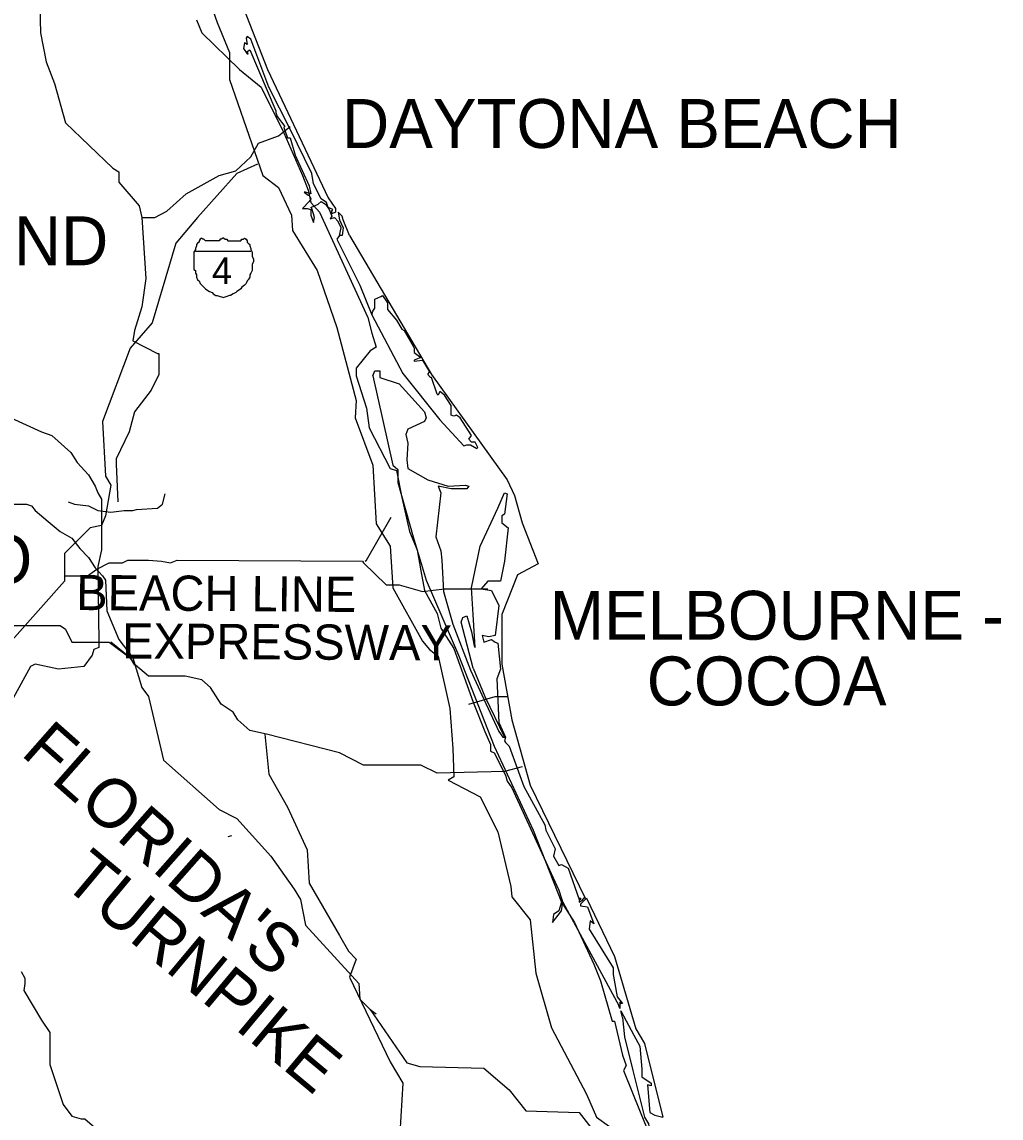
# Model space of a CAD drawing. Extents: x -827.9 to -798.1, y -2199.1 to -2182.2.
# Drawn here: x -805.79 to -804.889, y -2184.917 to -2183.909 of the extents above; entities that cross this region are included whole.
import ezdxf

# ---------------------------------------------------------------- set-up
doc = ezdxf.new("R2010")
doc.units = 0
for name, color, linetype in [('FLMap1', 7, 'Continuous'), ('FLMap2', 7, 'Continuous'), ('FLMap3', 7, 'Continuous'), ('TextMisc', 7, 'Continuous')]:
    doc.layers.add(name, color=color, linetype=linetype)

msp = doc.modelspace()

# ---------------------------------------------------------------- linework, layer by layer
at = {"layer": 'FLMap1'}
msp.add_line((-805.63, -2184.1195), (-805.5789, -2184.1195), dxfattribs=at)
for points in [[(-805.6037, -2184.1076), (-805.6047, -2184.1076), (-805.6062, -2184.1086), (-805.6072, -2184.1086), (-805.6082, -2184.1101), (-805.6101, -2184.1101), (-805.6111, -2184.1101), (-805.6126, -2184.1101), (-805.6136, -2184.1101), (-805.6146, -2184.1101), (-805.6161, -2184.1101), (-805.6171, -2184.1101), (-805.6186, -2184.1101), (-805.6206, -2184.1101), (-805.6221, -2184.1086), (-805.623, -2184.1086), (-805.624, -2184.1076), (-805.6255, -2184.1086), (-805.6265, -2184.1101), (-805.6265, -2184.1111), (-805.628, -2184.1121), (-805.629, -2184.1135), (-805.629, -2184.1145), (-805.63, -2184.117), (-805.63, -2184.118), (-805.6315, -2184.1205), (-805.6315, -2184.123), (-805.6315, -2184.124), (-805.6315, -2184.1269), (-805.6315, -2184.1294), (-805.6315, -2184.1314), (-805.6315, -2184.1339), (-805.6315, -2184.1364), (-805.63, -2184.1374), (-805.63, -2184.1398), (-805.629, -2184.1413), (-805.629, -2184.1433), (-805.628, -2184.1458), (-805.6265, -2184.1468), (-805.6255, -2184.1493), (-805.624, -2184.1508), (-805.6221, -2184.1527), (-805.6206, -2184.1542), (-805.6196, -2184.1552), (-805.6171, -2184.1567), (-805.6146, -2184.1577), (-805.6136, -2184.1587), (-805.6111, -2184.1602), (-805.6101, -2184.1602), (-805.6072, -2184.1612), (-805.6037, -2184.1622)], [(-805.6037, -2184.1076), (-805.6037, -2184.1076), (-805.6027, -2184.1086), (-805.6012, -2184.1086), (-805.6002, -2184.1101), (-805.5987, -2184.1101), (-805.5977, -2184.1101), (-805.5968, -2184.1101), (-805.5953, -2184.1101), (-805.5943, -2184.1101), (-805.5928, -2184.1101), (-805.5918, -2184.1101), (-805.5908, -2184.1101), (-805.5883, -2184.1101), (-805.5873, -2184.1086), (-805.5858, -2184.1086), (-805.5848, -2184.1076), (-805.5834, -2184.1086), (-805.5824, -2184.1101), (-805.5824, -2184.1111), (-805.5814, -2184.1121), (-805.5799, -2184.1135), (-805.5799, -2184.1145), (-805.5789, -2184.117), (-805.5789, -2184.118), (-805.5779, -2184.1205), (-805.5779, -2184.123), (-805.5779, -2184.124), (-805.5764, -2184.1269), (-805.5764, -2184.1294), (-805.5779, -2184.1314), (-805.5779, -2184.1339), (-805.5779, -2184.1364), (-805.5779, -2184.1374), (-805.5789, -2184.1398), (-805.5799, -2184.1413), (-805.5799, -2184.1433), (-805.5814, -2184.1458), (-805.5824, -2184.1468), (-805.5834, -2184.1493), (-805.5848, -2184.1508), (-805.5873, -2184.1527), (-805.5883, -2184.1542), (-805.5893, -2184.1552), (-805.5918, -2184.1567), (-805.5928, -2184.1577), (-805.5953, -2184.1587), (-805.5977, -2184.1602), (-805.5987, -2184.1602), (-805.6012, -2184.1612), (-805.6037, -2184.1622)]]:
    msp.add_lwpolyline(points, dxfattribs=at)
at = {"layer": 'FLMap2'}
for points in [[(-805.6444, -2183.7459), (-805.5635, -2183.9523)], [(-805.7734, -2183.8828), (-805.7724, -2183.9186), (-805.7674, -2183.9454), (-805.7595, -2183.9652), (-805.7496, -2184.0014), (-805.7059, -2184.0431), (-805.7004, -2184.0466), (-805.7004, -2184.056), (-805.6816, -2184.0778), (-805.6791, -2184.0887), (-805.6756, -2184.1448), (-805.6791, -2184.1706), (-805.6861, -2184.1924), (-805.6875, -2184.2019), (-805.6647, -2184.2138), (-805.6637, -2184.2138), (-805.6637, -2184.2331), (-805.6707, -2184.2475), (-805.6861, -2184.2673), (-805.691, -2184.2857), (-805.7029, -2184.3105)], [(-805.629, -2183.9067), (-805.624, -2183.9186), (-805.5893, -2183.9523), (-805.5695, -2183.9687), (-805.5486, -2184.0108), (-805.5313, -2184.05), (-805.5263, -2184.0634), (-805.5238, -2184.0748), (-805.5159, -2184.0838), (-805.4712, -2184.1805), (-805.4678, -2184.1949), (-805.4638, -2184.2078), (-805.4692, -2184.2113), (-805.4821, -2184.2272)], [(-805.5427, -2184.0074), (-805.5625, -2183.9687), (-805.5789, -2183.9245), (-805.5824, -2183.922), (-805.5834, -2183.9235), (-805.5824, -2183.9295), (-805.5848, -2183.928), (-805.5858, -2183.933), (-805.5824, -2183.9379), (-805.5814, -2183.9379), (-805.5824, -2183.9359), (-805.5799, -2183.9344), (-805.5561, -2183.9905), (-805.5561, -2183.992), (-805.5546, -2183.9955), (-805.5476, -2184.0049)], [(-805.5635, -2183.9523), (-805.5079, -2184.0704), (-805.501, -2184.0803), (-805.501, -2184.0838), (-805.5045, -2184.0853)], [(-805.6791, -2184.0887), (-805.6672, -2184.0887), (-805.6563, -2184.0828), (-805.6384, -2184.0669), (-805.6082, -2184.05), (-805.5928, -2184.0456), (-805.5789, -2184.0327), (-805.5719, -2184.0203), (-805.5536, -2184.0133), (-805.5427, -2184.0049)], [(-805.5476, -2184.0049), (-805.5486, -2184.0059), (-805.5452, -2184.0153), (-805.5427, -2184.0153), (-805.5382, -2184.0312), (-805.5253, -2184.0595), (-805.5238, -2184.0669), (-805.5288, -2184.0654), (-805.5298, -2184.0654), (-805.5263, -2184.0679), (-805.5253, -2184.0679), (-805.5238, -2184.0714), (-805.5253, -2184.0739), (-805.5313, -2184.0803), (-805.5273, -2184.0803), (-805.5238, -2184.0813), (-805.5238, -2184.0863), (-805.5213, -2184.0932), (-805.5203, -2184.0887), (-805.5213, -2184.0853), (-805.5228, -2184.0803), (-805.5238, -2184.0793), (-805.5169, -2184.0763), (-805.5144, -2184.0739), (-805.5104, -2184.0763), (-805.507, -2184.0813), (-805.5045, -2184.0872), (-805.506, -2184.0897), (-805.502, -2184.0887), (-805.4985, -2184.0922)], [(-805.5045, -2184.0853), (-805.5045, -2184.0828), (-805.5035, -2184.0813), (-805.5079, -2184.0793), (-805.5094, -2184.0748), (-805.5144, -2184.0714), (-805.5213, -2184.0575), (-805.5228, -2184.0481), (-805.5427, -2184.0074)], [(-805.4881, -2184.1051), (-805.4941, -2184.0907), (-805.495, -2184.0872), (-805.4985, -2184.0838), (-805.4975, -2184.0907), (-805.4941, -2184.0982), (-805.495, -2184.1051), (-805.4975, -2184.1051), (-805.496, -2184.0982), (-805.4985, -2184.0922)], [(-805.4975, -2184.1051), (-805.5, -2184.1086), (-805.4787, -2184.1508), (-805.4678, -2184.178)], [(-805.4881, -2184.1051), (-805.4127, -2184.2331), (-805.3432, -2184.3299), (-805.3363, -2184.3442), (-805.3293, -2184.3695), (-805.3145, -2184.4072), (-805.3338, -2184.4172), (-805.3482, -2184.4539), (-805.3482, -2184.4995), (-805.3388, -2184.5506), (-805.3219, -2184.6107), (-805.2713, -2184.7148)], [(-805.4678, -2184.178), (-805.4668, -2184.1746), (-805.4648, -2184.1721), (-805.4648, -2184.1637), (-805.4593, -2184.1612), (-805.4578, -2184.1602), (-805.4534, -2184.1671), (-805.4534, -2184.1731), (-805.4449, -2184.183), (-805.44, -2184.1914), (-805.438, -2184.1924), (-805.4296, -2184.2068), (-805.4286, -2184.2088), (-805.4286, -2184.2128), (-805.4226, -2184.2172), (-805.4286, -2184.2197), (-805.4286, -2184.2207), (-805.4211, -2184.2197), (-805.4147, -2184.2306)], [(-805.4678, -2184.178), (-805.439, -2184.2321), (-805.4052, -2184.2748), (-805.3829, -2184.2986)], [(-805.4821, -2184.2272), (-805.4821, -2184.2341), (-805.4727, -2184.2639), (-805.4702, -2184.2822), (-805.4509, -2184.3194), (-805.4449, -2184.3214), (-805.44, -2184.3462), (-805.433, -2184.3775), (-805.4261, -2184.3944), (-805.4226, -2184.4137), (-805.4191, -2184.4316), (-805.4077, -2184.4529), (-805.4043, -2184.4663), (-805.3923, -2184.4851), (-805.3745, -2184.5343), (-805.3636, -2184.5615), (-805.3586, -2184.5735), (-805.3586, -2184.5794), (-805.3551, -2184.5809), (-805.3447, -2184.6017), (-805.3432, -2184.6072), (-805.3388, -2184.6131), (-805.2956, -2184.7074), (-805.2911, -2184.7218)], [(-805.4668, -2184.2341), (-805.4648, -2184.2296), (-805.4603, -2184.2296), (-805.4603, -2184.2356), (-805.4425, -2184.2415), (-805.4191, -2184.2673), (-805.4177, -2184.2728), (-805.4191, -2184.2763)], [(-805.4668, -2184.2341), (-805.4484, -2184.3165), (-805.4439, -2184.3204), (-805.4439, -2184.3323), (-805.4296, -2184.3824), (-805.4177, -2184.4221), (-805.3879, -2184.4911), (-805.3551, -2184.5749), (-805.3194, -2184.6523), (-805.2931, -2184.7183)], [(-805.4008, -2184.252), (-805.4052, -2184.2485), (-805.4067, -2184.252), (-805.4077, -2184.251), (-805.4127, -2184.2356), (-805.4137, -2184.2356), (-805.4162, -2184.2331), (-805.4147, -2184.2306)], [(-805.3829, -2184.2986), (-805.3804, -2184.2976), (-805.377, -2184.2976), (-805.371, -2184.3011), (-805.37, -2184.3001), (-805.3725, -2184.2951), (-805.376, -2184.2951), (-805.3785, -2184.2926), (-805.376, -2184.2892), (-805.3864, -2184.2728), (-805.3899, -2184.2703), (-805.3923, -2184.2713), (-805.3948, -2184.2703), (-805.3948, -2184.2614), (-805.4008, -2184.252)], [(-805.7997, -2184.2728), (-805.7714, -2184.2857), (-805.762, -2184.2892), (-805.7446, -2184.3046), (-805.7386, -2184.314), (-805.7282, -2184.3254)], [(-805.4191, -2184.2763), (-805.4345, -2184.2832), (-805.4365, -2184.2882), (-805.4345, -2184.2961), (-805.4355, -2184.3115), (-805.4345, -2184.3194), (-805.4162, -2184.3299), (-805.3973, -2184.3358), (-805.3819, -2184.3348), (-805.3785, -2184.3358), (-805.3804, -2184.3383), (-805.3948, -2184.3383), (-805.4067, -2184.3358), (-805.4043, -2184.3418), (-805.4087, -2184.3824)], [(-805.7029, -2184.3105), (-805.7029, -2184.3155), (-805.7014, -2184.3502)], [(-805.7282, -2184.3254), (-805.7223, -2184.3358), (-805.7198, -2184.3418), (-805.7163, -2184.3477), (-805.7163, -2184.3681), (-805.7163, -2184.3944), (-805.7198, -2184.4097), (-805.7188, -2184.4792), (-805.7188, -2184.4841), (-805.7233, -2184.4861), (-805.7248, -2184.4911), (-805.7327, -2184.5015), (-805.756, -2184.504), (-805.7773, -2184.4995), (-805.7818, -2184.5015), (-805.8046, -2184.5437), (-805.8061, -2184.5506), (-805.8131, -2184.57), (-805.8141, -2184.5829), (-805.8344, -2184.5829), (-805.8547, -2184.5854), (-805.8622, -2184.5888)], [(-805.3745, -2184.503), (-805.3854, -2184.4608), (-805.3839, -2184.4564), (-805.3804, -2184.4549), (-805.376, -2184.4698), (-805.3735, -2184.4827), (-805.3725, -2184.4841), (-805.3745, -2184.4539), (-805.376, -2184.4291), (-805.368, -2184.3909), (-805.3517, -2184.3561), (-805.3457, -2184.3418), (-805.3432, -2184.3428), (-805.3457, -2184.3616), (-805.3482, -2184.3631), (-805.3482, -2184.3695), (-805.3422, -2184.374), (-805.3457, -2184.4048), (-805.3492, -2184.4231), (-805.3611, -2184.4231), (-805.367, -2184.4301), (-805.3576, -2184.4316), (-805.3507, -2184.4455), (-805.3541, -2184.4732), (-805.3601, -2184.4742), (-805.3661, -2184.4732), (-805.3646, -2184.4792), (-805.3576, -2184.4767), (-805.3541, -2184.4792), (-805.3517, -2184.4802), (-805.3492, -2184.504)], [(-805.4087, -2184.3824), (-805.4043, -2184.3953), (-805.4033, -2184.4038), (-805.4018, -2184.4326), (-805.3933, -2184.4628), (-805.377, -2184.505)], [(-805.8121, -2184.4549), (-805.8026, -2184.4638), (-805.7545, -2184.4638), (-805.7496, -2184.4673), (-805.7436, -2184.4792), (-805.7094, -2184.4792), (-805.69, -2184.4936), (-805.6861, -2184.5005)], [(-805.3293, -2184.5938), (-805.3457, -2184.5983), (-805.4077, -2184.5997), (-805.4226, -2184.5923), (-805.4752, -2184.5923), (-805.4975, -2184.5809), (-805.5645, -2184.564), (-805.5799, -2184.5606), (-805.5908, -2184.5506), (-805.5953, -2184.5437), (-805.6062, -2184.5362), (-805.6161, -2184.5209), (-805.624, -2184.5139), (-805.6394, -2184.5104), (-805.6732, -2184.5104), (-805.6851, -2184.5005), (-805.69, -2184.4936), (-805.7079, -2184.4792)], [(-805.377, -2184.505), (-805.3646, -2184.5318), (-805.3507, -2184.5615), (-805.3472, -2184.5665), (-805.3457, -2184.5665)], [(-805.3745, -2184.503), (-805.3636, -2184.5293), (-805.3457, -2184.5665)], [(-805.3492, -2184.504), (-805.3527, -2184.5129), (-805.3507, -2184.5531), (-805.3447, -2184.5665), (-805.3457, -2184.57), (-805.3447, -2184.5715), (-805.3412, -2184.5749)], [(-805.566, -2184.564), (-805.5625, -2184.6007), (-805.5452, -2184.631), (-805.5273, -2184.6702), (-805.5253, -2184.701), (-805.4975, -2184.7491), (-805.4891, -2184.7635), (-805.4821, -2184.7709), (-805.4881, -2184.7873), (-805.4509, -2184.8652), (-805.439, -2184.885), (-805.4484, -2185.0383), (-805.4484, -2185.0597), (-805.4345, -2185.0537), (-805.4261, -2185.0552), (-805.4127, -2185.0646)], [(-805.3412, -2184.5749), (-805.3279, -2184.6121), (-805.3085, -2184.6474), (-805.3075, -2184.6523), (-805.2991, -2184.6692), (-805.3006, -2184.6761), (-805.2956, -2184.6846), (-805.2931, -2184.6836), (-805.2872, -2184.6871), (-805.2768, -2184.7158)], [(-805.2931, -2184.7183), (-805.2956, -2184.7263), (-805.3006, -2184.7297), (-805.3016, -2184.7372), (-805.2931, -2184.7263), (-805.2921, -2184.7183)], [(-805.2921, -2184.7183), (-805.2405, -2184.8136)], [(-805.2768, -2184.7148), (-805.2758, -2184.7148), (-805.2758, -2184.7158), (-805.2768, -2184.7168), (-805.2768, -2184.7183), (-805.2743, -2184.7168), (-805.2713, -2184.7134)], [(-805.2703, -2184.7148), (-805.2758, -2184.7203), (-805.2758, -2184.7218), (-805.2693, -2184.7228), (-805.2634, -2184.7382), (-805.2668, -2184.7357), (-805.2678, -2184.7431), (-805.2455, -2184.7788), (-805.2455, -2184.7848), (-805.242, -2184.8056), (-805.2371, -2184.8116), (-805.2385, -2184.8116), (-805.2395, -2184.8101), (-805.2395, -2184.8161)], [(-805.2703, -2184.7148), (-805.2445, -2184.7684), (-805.2247, -2184.8349), (-805.2167, -2184.8483), (-805.1999, -2184.9163)], [(-805.2911, -2184.7218), (-805.2812, -2184.7372), (-805.2634, -2184.7754), (-805.2574, -2184.7908), (-805.2465, -2184.828), (-805.2445, -2184.828), (-805.2371, -2184.8592), (-805.2336, -2184.8686), (-805.2361, -2184.8731), (-805.2202, -2184.9128), (-805.2152, -2184.9247), (-805.2142, -2184.9867), (-805.1939, -2185.0284), (-805.1835, -2185.0517)], [(-805.7902, -2184.7823), (-805.7868, -2184.7883), (-805.7868, -2184.7932), (-805.7878, -2184.7997), (-805.7714, -2184.827), (-805.7639, -2184.8384), (-805.7639, -2184.8677), (-805.7515, -2184.9044), (-805.7436, -2184.9153), (-805.7352, -2184.9178), (-805.7317, -2184.9178), (-805.7208, -2184.9272), (-805.7188, -2184.949), (-805.7173, -2184.9594), (-805.7069, -2184.9773), (-805.7029, -2184.9907), (-805.692, -2185.0001), (-805.691, -2185.012), (-805.6791, -2185.0408)], [(-805.2395, -2184.8161), (-805.2405, -2184.8136)], [(-805.2371, -2184.8245), (-805.2385, -2184.8185), (-805.2266, -2184.8409), (-805.2212, -2184.8508), (-805.2192, -2184.8721), (-805.2192, -2184.8791), (-805.2108, -2184.885), (-805.2108, -2184.8875), (-805.2142, -2184.8865), (-805.2118, -2184.9118), (-805.2073, -2184.9143), (-805.1999, -2184.9163), (-805.1999, -2184.9163)], [(-805.2371, -2184.8245), (-805.2351, -2184.8424), (-805.2276, -2184.8731), (-805.2167, -2184.9163), (-805.2132, -2184.9222), (-805.2118, -2184.9307), (-805.1711, -2185.0264), (-805.1497, -2185.0656)]]:
    msp.add_lwpolyline(points, dxfattribs=at)
at = {"layer": 'FLMap3'}
for points in [[(-805.634, -2183.8412), (-805.6101, -2183.9091), (-805.5987, -2183.9369), (-805.5987, -2183.9617), (-805.568, -2184.05), (-805.5536, -2184.061), (-805.5417, -2184.0863), (-805.5407, -2184.1006), (-805.5179, -2184.1374), (-805.5, -2184.1899), (-805.4821, -2184.2569), (-805.4831, -2184.2728), (-805.4668, -2184.3165), (-805.4638, -2184.3705), (-805.4509, -2184.3909), (-805.4484, -2184.4291), (-805.4211, -2184.4782), (-805.4147, -2184.4861), (-805.4067, -2184.4921), (-805.3958, -2184.5402)], [(-805.5729, -2184.0396), (-805.5918, -2184.0481), (-805.628, -2184.0887), (-805.6479, -2184.1121), (-805.6697, -2184.1855), (-805.69, -2184.2088), (-805.7153, -2184.2763), (-805.7128, -2184.3264), (-805.7079, -2184.3348), (-805.7128, -2184.3631), (-805.7163, -2184.372), (-805.7267, -2184.374), (-805.7505, -2184.3978), (-805.7505, -2184.4231), (-805.8428, -2184.5268)], [(-806.0328, -2184.1875), (-806.0314, -2184.1899), (-806.0279, -2184.1949), (-806.0125, -2184.2009), (-805.9847, -2184.2247), (-805.9708, -2184.2366), (-805.9262, -2184.2832), (-805.8701, -2184.3179), (-805.8666, -2184.3214), (-805.8473, -2184.3442), (-805.825, -2184.3512), (-805.8215, -2184.3512), (-805.8165, -2184.3522), (-805.7853, -2184.3522), (-805.7808, -2184.3537), (-805.7773, -2184.3581)], [(-805.7471, -2184.3502), (-805.7411, -2184.3522), (-805.7282, -2184.3537), (-805.7198, -2184.3581), (-805.7079, -2184.3596), (-805.6955, -2184.3581), (-805.6875, -2184.3581), (-805.6841, -2184.3571), (-805.6647, -2184.3561), (-805.6603, -2184.3522), (-805.6578, -2184.3428)], [(-805.7773, -2184.3581), (-805.7654, -2184.3681), (-805.7545, -2184.3775), (-805.7436, -2184.3834), (-805.7362, -2184.3929), (-805.7282, -2184.4013), (-805.7223, -2184.4107), (-805.7153, -2184.4182), (-805.7128, -2184.4221), (-805.7114, -2184.4504), (-805.7004, -2184.4767)], [(-805.4737, -2184.4048), (-805.4727, -2184.4038), (-805.4499, -2184.3641)], [(-805.7505, -2184.4182), (-805.7292, -2184.4182), (-805.7208, -2184.4122), (-805.7094, -2184.4063), (-805.697, -2184.4063), (-805.692, -2184.4038), (-805.6732, -2184.4038), (-805.6612, -2184.4048), (-805.6528, -2184.4063), (-805.6469, -2184.4038), (-805.4762, -2184.4048), (-805.4752, -2184.4063), (-805.4544, -2184.4266), (-805.4425, -2184.4266), (-805.4211, -2184.4326), (-805.4008, -2184.4301), (-805.3611, -2184.4301)], [(-805.7004, -2184.4767), (-805.6875, -2184.4936), (-805.6791, -2184.5209), (-805.6732, -2184.5293), (-805.6593, -2184.5878), (-805.6082, -2184.633), (-805.5918, -2184.6414), (-805.5605, -2184.6761), (-805.5392, -2184.7064), (-805.5332, -2184.7158), (-805.5288, -2184.7397), (-805.4797, -2184.7932), (-805.4787, -2184.8076), (-805.4692, -2184.817), (-805.4638, -2184.821)], [(-805.3785, -2184.5362), (-805.3541, -2184.5293), (-805.3432, -2184.5293)], [(-805.3958, -2184.5402), (-805.3933, -2184.5769), (-805.3923, -2184.6032), (-805.3973, -2184.6062), (-805.368, -2184.6216), (-805.3517, -2184.6538), (-805.3398, -2184.7039), (-805.3388, -2184.7134), (-805.3219, -2184.7347), (-805.3169, -2184.7838), (-805.3025, -2184.8339), (-805.2703, -2184.8949), (-805.2609, -2184.9163), (-805.249, -2184.9247)], [(-805.5968, -2184.6573), (-805.6002, -2184.6583)], [(-805.4692, -2184.817), (-805.4355, -2184.8662), (-805.4236, -2184.8696), (-805.3646, -2184.8711), (-805.3412, -2184.891), (-805.3259, -2184.9103), (-805.2768, -2184.9118), (-805.2599, -2184.9341), (-805.2371, -2184.9798), (-805.2361, -2185.0095), (-805.2152, -2185.0597), (-805.179, -2185.1147), (-805.1651, -2185.1495), (-805.1324, -2185.1877), (-805.115, -2185.2278), (-805.1185, -2185.3117), (-805.1368, -2185.3429), (-805.1334, -2185.5186)]]:
    msp.add_lwpolyline(points, dxfattribs=at)

# ---------------------------------------------------------------- texts
at = {"layer": 'TextMisc'}
for s, height, p in [('DAYTONA BEACH', 0.045, (-805.4951, -2184.0246)), ('DELAND', 0.045, (-805.9542, -2184.1325)), ('4', 0.0247, (-805.6147, -2184.1498)), ('ORLANDO', 0.045, (-806.0776, -2184.4255)), ('MELBOURNE -', 0.045, (-805.3041, -2184.477)), ('COCOA', 0.045, (-805.2148, -2184.5374))]:
    msp.add_text(s, height=height, dxfattribs=at).set_placement(p)
for s, height, rotation, p in [('BEACH LINE', 0.0324, 359.6118, (-805.7397, -2184.4497)), ('EXPRESSWAY', 0.0324, 359.6441, (-805.6975, -2184.4942)), ("FLORIDA'S", 0.045, 318.5663, (-805.7916, -2184.5824)), ('TURNPIKE', 0.045, 320.1263, (-805.7538, -2184.7015))]:
    msp.add_text(s, height=height, rotation=rotation, dxfattribs=at).set_placement(p)

doc.saveas('drawing.dxf')
